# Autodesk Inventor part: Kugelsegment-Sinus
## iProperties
Shininess: 64.0
Length Units: 11272
Angle Units: 11279
Time Units: 11290
Mass Units: 11286
Length Display Precision: 3
Angle Display Precision: 2
Compacted: True
Part Number: Kugelsegment-Sinus
Document SubType Name: Modeling
Created: 2005-11
Designer: W. Holzwarth
Manufacturer: Standard
Standards Organization: Custom
Density: 0.0
Volumn: 0.0
Area: 0.0
PropertySet Name: Model Information
Control State: 0
Master: False
Checked Out: False
Diam: 2.000 in
Author: W. Holzwarth
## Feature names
1. Revolution1
2. Trennen2
3. Trennen3
4. Spiegeln1 [Mirror]
